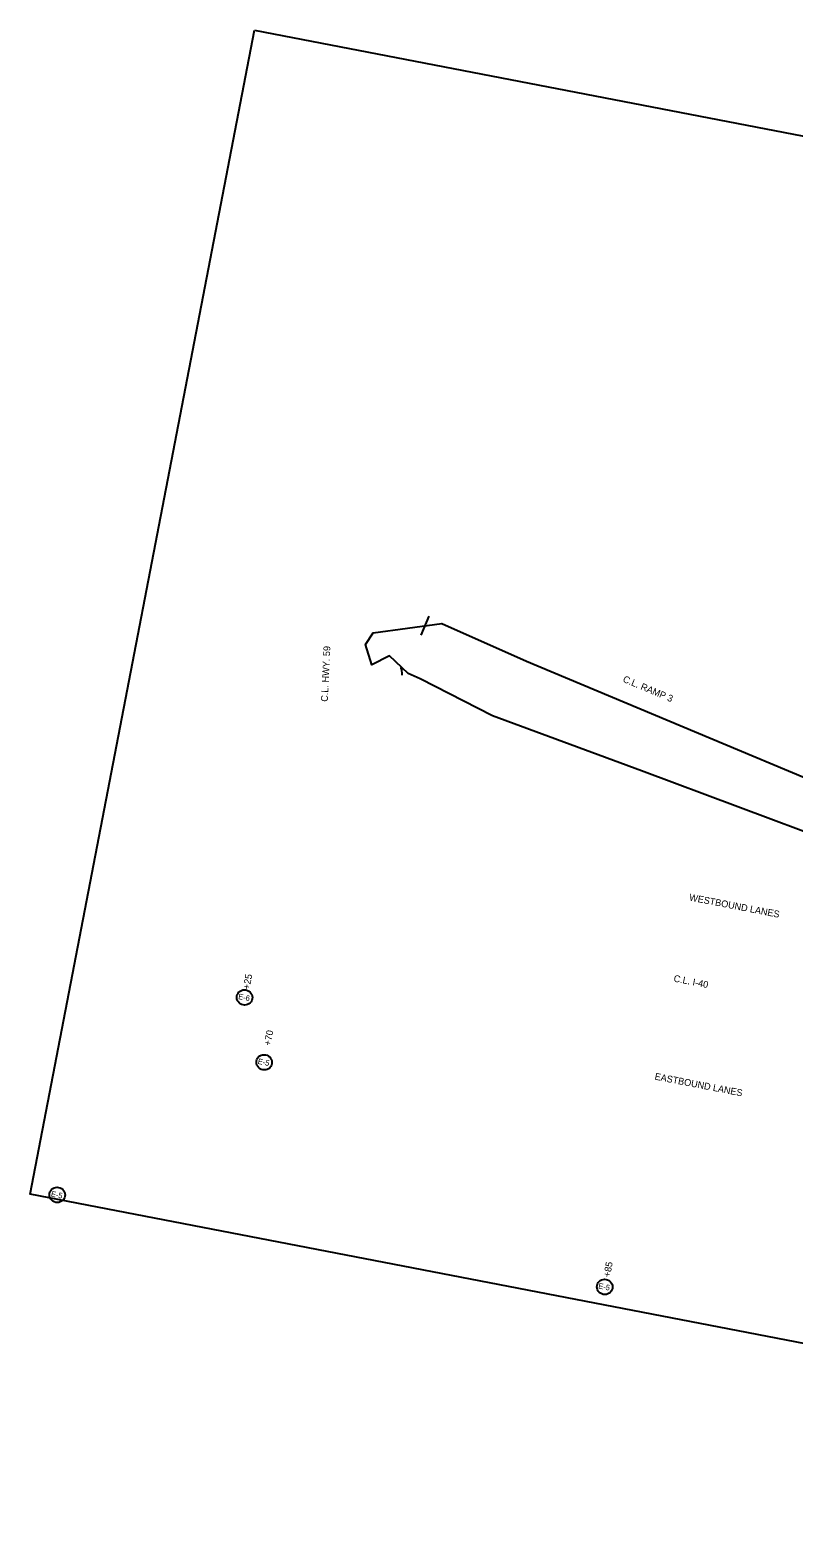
# Model space of a CAD drawing. Extents: x 610464 to 612219, y 418975 to 420301.
# Drawn here: x 610464 to 611136, y 418975 to 420301 of the extents above; entities that cross this region are included whole.
import ezdxf

# ---------------------------------------------------------------- set-up
doc = ezdxf.new("R2010")
doc.units = 0
for name, color, linetype in [('Default', 7, 'Continuous'), ('R_Draft', 7, 'Continuous'), ('R_Guardrail', 7, 'Continuous'), ('R_Island', 7, 'Continuous'), ('R_OBLI_EXIST', 7, 'Continuous')]:
    doc.layers.add(name, color=color, linetype=linetype)

msp = doc.modelspace()

# ---------------------------------------------------------------- linework, layer by layer
for points in [[(610661.8, 420300.9), (611918.6, 420058.3), (611909.2, 420009.6), (612023.4, 419987.6), (612218.9, 419949.8), (612215.9, 419934.6), (612030.7, 418975.1), (610464.3, 419277.4)], [(610807.4, 419730.5), (610796.9, 419735.1), (610780.6, 419750.8), (610764.8, 419742.9), (610759.3, 419760.5), (610766.2, 419770.9), (610826.5, 419779.1), (610901, 419746), (611086.6, 419668.4), (611311.1, 419574.6), (611478.1, 419527.3), (611612.9, 419500), (611678.9, 419484.9), (611756.4, 419465.5), (611769.5, 419458.8), (611768.7, 419455.3), (611750.9, 419458.3), (611670.6, 419464.3), (611497.9, 419490.5), (611300.1, 419528.7), (611171.8, 419586.2), (611002.2, 419649.5), (610871.2, 419698)]]:
    msp.add_lwpolyline(points, close=True)
at = {"layer": 'R_Guardrail'}
msp.add_lwpolyline([(610791.7, 419733.8), (610791.3, 419739.4), (610789.9, 419739.4)], dxfattribs=at)
at = {"layer": 'R_Island'}
for centre in [(610652.9, 419450.3), (610670.2, 419393.2), (610488.1, 419276.6), (610969.8, 419195.7)]:
    msp.add_ellipse(centre, major_axis=(-6.76, 1.31), ratio=0.97521, dxfattribs=at)
at = {"layer": 'R_OBLI_EXIST'}
msp.add_lwpolyline([(610808.4, 419768.9), (610815.4, 419785.6)], dxfattribs=at)

# ---------------------------------------------------------------- texts
at = {"layer": 'Default'}
for s, rotation, p in [('C.L. HWY. 59', 87.2385, (610726.1, 419710.2)), ('C.L. RAMP 3', 337.1402, (610985.2, 419728))]:
    msp.add_text(s, height=6, rotation=rotation, dxfattribs=at).set_placement(p)
at = {"layer": 'R_Draft'}
for s, rotation, p in [('WESTBOUND LANES', 349.0745, (611043.8, 419535.6)), ('C.L. I-40', 349.0501, (611030.1, 419464.3)), ('EASTBOUND LANES', 349.0745, (611013.4, 419378.1))]:
    msp.add_text(s, height=6, rotation=rotation, dxfattribs=at).set_placement(p)
at = {"layer": 'R_Island'}
for s, height, rotation, p in [('+25', 6, 79.1477, (610657.2, 419456.9)), ('E-6', 4.88, 349.0745, (610647.1, 419448.9)), ('+70', 6, 79.1477, (610675.8, 419407.5)), ('E-5', 4.88, 349.0745, (610664.3, 419391.9)), ('E-5', 4.88, 349.0745, (610482.3, 419275.3)), ('+85', 6, 79.1477, (610974.4, 419203.9)), ('E-5', 4.88, 349.0745, (610963.9, 419194.4))]:
    msp.add_text(s, height=height, rotation=rotation, dxfattribs=at).set_placement(p)

doc.saveas('drawing.dxf')
